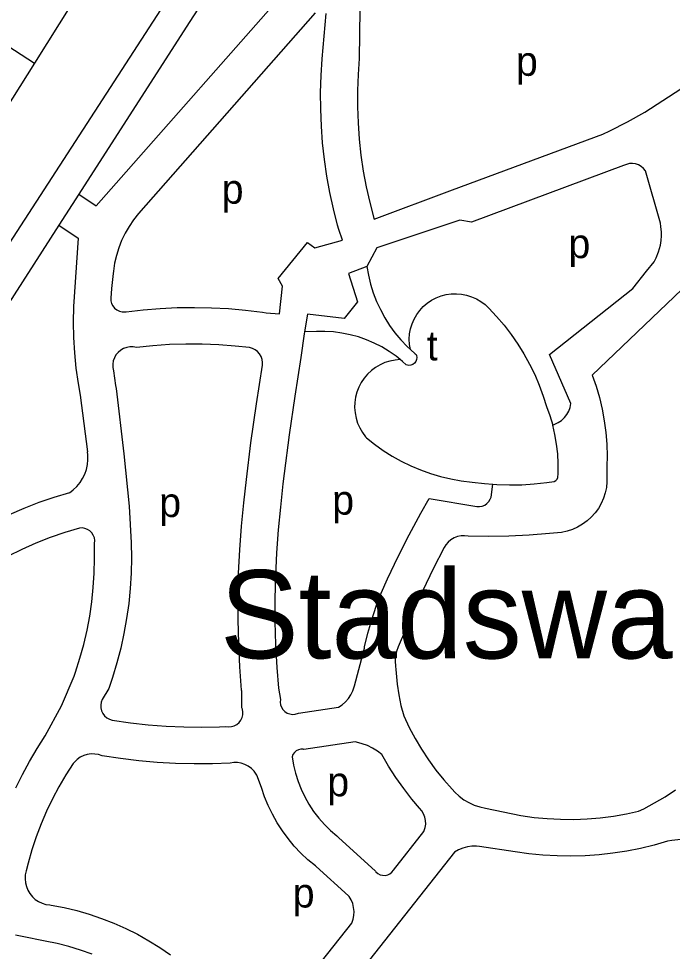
# Model space of a CAD drawing. Extents: x 161141 to 163125, y 381621 to 383200.
# Drawn here: x 161502.1 to 161591, y 381873.7 to 382000.5 of the extents above; entities that cross this region are included whole.
import ezdxf

# ---------------------------------------------------------------- set-up
doc = ezdxf.new("R2010")
doc.units = 0
for name, color, linetype in [('BLT_Basislijn', 7, 'Continuous'), ('BLT_Centroide', 7, 'Continuous'), ('BLT_Sport_parknaam', 7, 'Continuous')]:
    doc.layers.add(name, color=color, linetype=linetype)

msp = doc.modelspace()

# ---------------------------------------------------------------- linework, layer by layer
at = {"layer": 'BLT_Basislijn'}
for p, q in [((161478.82, 381936.02), (161528.43, 382012.47)), ((161509.31, 382002.51), (161504.27, 381994.49)), ((161499.76, 381997.41), (161504.27, 381994.49)), ((161510.29, 381976.65), (161507.59, 381972.44)), ((161507.59, 381972.44), (161460.42, 381899.15)), ((161507.59, 381972.44), (161510.24, 381970.68)), ((161510.24, 381970.68), (161509.59, 381961.37)), ((161510.47, 381949.31), (161511.48, 381941.63))]:
    msp.add_line(p, q, dxfattribs=at)
for points in [[(161510.29, 381976.65), (161512.67, 381975.06), (161540.81, 382007.02), (161543.84, 382010.43), (161567.14, 382036.81), (161578.53, 382051.26), (161578.78, 382051.57), (161578.98, 382051.94), (161579.1, 382052.33), (161579.14, 382052.74), (161579.1, 382053.16), (161578.99, 382053.55), (161578.8, 382053.92), (161578.54, 382054.24), (161578.23, 382054.51), (161577.87, 382054.71), (161567.03, 382064.29)], [(161567.03, 382064.29), (161566.63, 382063.69), (161525.32, 382000), (161510.29, 381976.65)], [(161587.29, 381987.83), (161601.2, 381996.85), (161601.52, 381997.05), (161601.84, 381997.33), (161602.09, 381997.67), (161602.27, 381998.05), (161602.39, 381998.45), (161602.42, 381998.87), (161602.37, 381999.29), (161602.24, 381999.69), (161602.04, 382000.06), (161571.03, 382028.64)], [(161548.56, 382005.09), (161548.43, 381995.12), (161548.27, 381992.93), (161548.19, 381990.74), (161548.19, 381988.54), (161548.27, 381986.35), (161548.43, 381984.16), (161548.67, 381981.98), (161548.99, 381979.81), (161549.39, 381977.65), (161549.86, 381975.51), (161550.42, 381973.38), (161550.46, 381973.24), (161561.11, 381977.23), (161581.58, 381984.83), (161582.51, 381985.28), (161584.92, 381986.52), (161587.29, 381987.83)], [(161542.45, 382001.33), (161518.42, 381974.02), (161517.74, 381973.17), (161517.14, 381972.27), (161516.6, 381971.34), (161516.13, 381970.36), (161515.74, 381969.35), (161515.42, 381968.32), (161515.18, 381967.26), (161515.01, 381966.19), (161514.98, 381965.85), (161514.76, 381963.85), (161514.65, 381962.52), (161514.67, 381962.15), (161514.77, 381961.78), (161514.95, 381961.45), (161515.18, 381961.15), (161515.48, 381960.92), (161515.82, 381960.75), (161516.18, 381960.66), (161516.56, 381960.64), (161516.74, 381960.67), (161519.05, 381960.93), (161521.37, 381961.12), (161523.69, 381961.23), (161526.02, 381961.26), (161528.34, 381961.22), (161530.67, 381961.09), (161532.98, 381960.88), (161535.29, 381960.59), (161535.8, 381960.51), (161537.6, 381960.36), (161538.01, 381964.13), (161537.4, 381965.18), (161541.41, 381970.1), (161542.41, 381969.37), (161546.17, 381970.38), (161545.65, 381971.87)], [(161545.65, 381971.87), (161545.49, 381972.43), (161544.93, 381974.65), (161544.44, 381976.88), (161544.04, 381979.13), (161543.71, 381981.39), (161543.46, 381983.66), (161543.29, 381985.93), (161543.2, 381988.22), (161543.19, 381990.5), (161543.26, 381992.79), (161543.41, 381995.06), (161543.95, 382001.24)], [(161504.27, 381994.49), (161492.03, 381975.07)], [(161574.74, 381945.25), (161575.02, 381945.35), (161575.5, 381945.59), (161575.94, 381945.89), (161576.33, 381946.26), (161576.66, 381946.68), (161576.92, 381947.15), (161577.11, 381947.64), (161577.22, 381948.17), (161574.32, 381954.84), (161585.64, 381963.85), (161587.52, 381966.17), (161588.52, 381967.45), (161588.8, 381967.98), (161589.13, 381968.8), (161589.41, 381969.72), (161589.51, 381970.36), (161589.55, 381970.99), (161589.54, 381971.51), (161589.46, 381972.26), (161589.41, 381972.7), (161587.38, 381979.82), (161587.11, 381980.15), (161586.79, 381980.43), (161586.43, 381980.64), (161586.02, 381980.77), (161585.61, 381980.83), (161585.18, 381980.81), (161584.77, 381980.71), (161584.39, 381980.54), (161563.72, 381972.86), (161562.13, 381973.14), (161550.81, 381969.36), (161549.46, 381966.84)], [(161549.46, 381966.84), (161546.99, 381965.85), (161548.18, 381962.02), (161546.37, 381959.76), (161541.4, 381960.34), (161540.98, 381957.94)], [(161549.46, 381966.84), (161549.68, 381965.62), (161549.98, 381964.41), (161550.35, 381963.23), (161550.8, 381962.07), (161551.32, 381960.95), (161551.91, 381959.86), (161552.57, 381958.81), (161553.3, 381957.81), (161554.09, 381956.86), (161554.94, 381955.96), (161555.39, 381955.53)], [(161592.31, 381963.67), (161580.13, 381952.04), (161580.65, 381950.52), (161581.1, 381948.98), (161581.46, 381947.41), (161581.75, 381945.83), (161581.96, 381944.24), (161582.09, 381942.63), (161582.14, 381941.02), (161582.12, 381939.65), (161582.12, 381937.54), (161582.04, 381936.77), (161581.88, 381936.02), (161581.64, 381935.29), (161581.33, 381934.59), (161580.95, 381933.92), (161580.5, 381933.3), (161579.98, 381932.73), (161579.42, 381932.21), (161578.8, 381931.76), (161578.13, 381931.37), (161577.43, 381931.05), (161576.7, 381930.81), (161575.95, 381930.65), (161574.31, 381930.49), (161571.55, 381930.28), (161568.79, 381930.15), (161566.03, 381930.11), (161563.26, 381930.14), (161562.77, 381930.2), (161562.28, 381930.17), (161561.8, 381930.07), (161561.34, 381929.89), (161560.91, 381929.64), (161560.53, 381929.32), (161560.21, 381928.95), (161559.99, 381928.61), (161558.5, 381925.7), (161557.07, 381922.75), (161555.72, 381919.77), (161554.44, 381916.75), (161554.02, 381915.71), (161553.74, 381915.1), (161553.52, 381914.47), (161553.39, 381913.81), (161553.34, 381913.14), (161553.36, 381912.47), (161553.43, 381912.02), (161553.46, 381911.48), (161553.6, 381910.01), (161553.81, 381908.55), (161554.11, 381907.1), (161554.49, 381905.68)], [(161555.39, 381955.53), (161555.27, 381956.23), (161555.24, 381956.93), (161555.29, 381957.64), (161555.42, 381958.33), (161555.62, 381959.01), (161555.9, 381959.66), (161556.25, 381960.27), (161556.67, 381960.85), (161557.15, 381961.36), (161557.69, 381961.83), (161558.27, 381962.22), (161558.9, 381962.55), (161559.56, 381962.81), (161560.24, 381962.99), (161560.94, 381963.1), (161561.65, 381963.12), (161562.35, 381963.06), (161563.04, 381962.93), (161563.72, 381962.71), (161564.36, 381962.43), (161564.97, 381962.07), (161565.54, 381961.64), (161566.04, 381961.17), (161567.12, 381960.02), (161568.15, 381958.82), (161569.11, 381957.57), (161570.01, 381956.27), (161570.84, 381954.93), (161571.6, 381953.55), (161572.3, 381952.13), (161572.91, 381950.67), (161573.46, 381949.19), (161573.9, 381947.78), (161574.36, 381946.54), (161574.74, 381945.25)], [(161509.59, 381961.37), (161509.55, 381959.27), (161509.6, 381957.17), (161509.72, 381955.07), (161509.92, 381952.98), (161510.2, 381950.9), (161510.47, 381949.31)], [(161540.98, 381957.94), (161540.93, 381957.64), (161540.5, 381954.43), (161539.66, 381949.18), (161538.9, 381943.92), (161538.22, 381938.65), (161538.05, 381937.27), (161537.73, 381934.09), (161537.42, 381930.98), (161537.18, 381927.87), (161537.03, 381924.75), (161536.96, 381921.63), (161536.97, 381918.5), (161537.06, 381915.38), (161537.23, 381912.26), (161537.44, 381909.48), (161537.71, 381907.94), (161537.68, 381907.57), (161537.74, 381907.2), (161537.87, 381906.86), (161538.07, 381906.54), (161538.33, 381906.28), (161538.65, 381906.08), (161539, 381905.95), (161539.37, 381905.9), (161539.74, 381905.92), (161540.18, 381906.07), (161545.63, 381906.86), (161546.13, 381907.2), (161546.58, 381907.59), (161546.98, 381908.04), (161547.31, 381908.54), (161547.57, 381909.08), (161547.75, 381909.65), (161547.79, 381909.78), (161549.14, 381914.92), (161549.17, 381915.06), (161549.62, 381916.93), (161550.14, 381918.77), (161550.74, 381920.6), (161551.41, 381922.39), (161552.3, 381924.34), (161553.73, 381927.35), (161555.24, 381930.32), (161556.82, 381933.26), (161557.94, 381935.24), (161564.43, 381934.18), (161564.8, 381934.16), (161565.16, 381934.22), (161565.51, 381934.36), (161565.81, 381934.57), (161566.07, 381934.84), (161566.26, 381935.15), (161566.36, 381935.44), (161566.62, 381937.19)], [(161554.01, 381954.15), (161553.45, 381954.61), (161552.5, 381955.28), (161551.51, 381955.87), (161550.48, 381956.4), (161549.42, 381956.86), (161548.32, 381957.24), (161547.21, 381957.54), (161546.07, 381957.77), (161544.92, 381957.92), (161543.77, 381957.99), (161542.61, 381957.98), (161540.98, 381957.94)], [(161532.46, 381909.03), (161532.45, 381909.21), (161532.21, 381912.38), (161532.05, 381915.57), (161531.96, 381918.75), (161531.96, 381921.94), (161532.04, 381925.12), (161532.2, 381928.3), (161532.44, 381931.48), (161532.76, 381934.65), (161533.09, 381937.86), (161533.71, 381942.83), (161534.45, 381948.13), (161535.27, 381953.41), (161535.29, 381953.78), (161535.23, 381954.19), (161535.1, 381954.58), (161534.89, 381954.93), (161534.62, 381955.24), (161534.29, 381955.49), (161533.92, 381955.67), (161533.53, 381955.78), (161531.56, 381955.99), (161529.33, 381956.16), (161527.1, 381956.25), (161524.86, 381956.26), (161522.62, 381956.19), (161520.39, 381956.04), (161518.16, 381955.81), (161517.72, 381955.89), (161517.26, 381955.89), (161516.82, 381955.81), (161516.39, 381955.66), (161516, 381955.43), (161515.65, 381955.14), (161515.36, 381954.79), (161515.14, 381954.4), (161514.99, 381953.97), (161514.91, 381953.53), (161514.92, 381953.08), (161515.01, 381952.62), (161515.31, 381950.65), (161515.39, 381950.22), (161516.42, 381941.34), (161517.14, 381934.23), (161517.43, 381929.23), (161517.46, 381927.17), (161517.42, 381925.1), (161517.29, 381923.04), (161517.09, 381920.99), (161516.8, 381918.94), (161516.44, 381916.91), (161516, 381914.89), (161515.48, 381912.89), (161514.88, 381910.91), (161514.38, 381909.43), (161513.48, 381907.94), (161513.34, 381907.57), (161513.28, 381907.17), (161513.3, 381906.77), (161513.4, 381906.38), (161513.58, 381906.02), (161513.82, 381905.7), (161514.12, 381905.43), (161514.47, 381905.23), (161514.85, 381905.1), (161517.34, 381904.74), (161519.75, 381904.47), (161522.17, 381904.29), (161524.6, 381904.18), (161527.02, 381904.15), (161529.45, 381904.21), (161530.31, 381904.24), (161530.69, 381904.2), (161531.08, 381904.24), (161531.45, 381904.35), (161531.79, 381904.54), (161532.09, 381904.79), (161532.33, 381905.1), (161532.5, 381905.45), (161532.59, 381905.83), (161532.61, 381906.21), (161532.55, 381906.6), (161532.49, 381906.78), (161532.46, 381909.03)], [(161555.39, 381955.53), (161556.04, 381954.95), (161556.17, 381954.83), (161556.21, 381954.73), (161556.26, 381954.45), (161556.23, 381954.16), (161556.12, 381953.9), (161555.95, 381953.67), (161555.72, 381953.49), (161555.45, 381953.39), (161555.17, 381953.37), (161554.83, 381953.44), (161554.34, 381953.88), (161554.01, 381954.15)], [(161554.01, 381954.15), (161553.31, 381954.09), (161552.61, 381953.96), (161551.93, 381953.74), (161551.28, 381953.45), (161550.66, 381953.09), (161550.09, 381952.66), (161549.57, 381952.17), (161549.1, 381951.62), (161548.71, 381951.03), (161548.38, 381950.4), (161548.12, 381949.73), (161547.94, 381949.04), (161547.83, 381948.33), (161547.81, 381947.62), (161547.87, 381946.9), (161548, 381946.2), (161548.21, 381945.52), (161548.5, 381944.87), (161548.86, 381944.25), (161549.29, 381943.67), (161549.41, 381943.53), (161550.53, 381942.63), (161551.7, 381941.79), (161552.91, 381941.02), (161554.16, 381940.32), (161555.45, 381939.69), (161556.77, 381939.14), (161558.13, 381938.65), (161559.5, 381938.25), (161560.9, 381937.92), (161562.31, 381937.67), (161563.81, 381937.49), (161565.49, 381937.28), (161566.62, 381937.19)], [(161566.62, 381937.19), (161567.17, 381937.15), (161568.86, 381937.1), (161570.56, 381937.13), (161572.24, 381937.24), (161573.93, 381937.42), (161574.95, 381937.58), (161575.17, 381937.69), (161575.33, 381937.87), (161575.44, 381938.14), (161575.47, 381938.68), (161575.48, 381940.01), (161575.42, 381941.33), (161575.27, 381942.66), (161575.04, 381943.97), (161574.74, 381945.25)], [(161509.02, 381936.05), (161509.55, 381936.45), (161510.04, 381936.91), (161510.47, 381937.42), (161510.83, 381937.98), (161511.12, 381938.59), (161511.34, 381939.22), (161511.49, 381939.87), (161511.55, 381940.54), (161511.53, 381941.21), (161511.48, 381941.63)], [(161509.02, 381936.05), (161506.93, 381935.41), (161504.87, 381934.7), (161502.84, 381933.91), (161500.83, 381933.05), (161498.86, 381932.11), (161496.93, 381931.11), (161495.03, 381930.03), (161493.72, 381929.23)], [(161501.76, 381895.9), (161502.65, 381897.72), (161503.61, 381899.5), (161504.64, 381901.25), (161505.74, 381902.96), (161507.96, 381907.07), (161509.67, 381911.11), (161509.86, 381911.64), (161510.45, 381913.52), (161510.98, 381915.41), (161511.42, 381917.33), (161511.79, 381919.26), (161512.08, 381921.2), (161512.28, 381923.16), (161512.41, 381925.12), (161512.46, 381927.09), (161512.43, 381929.05), (161512.45, 381929.15), (161512.47, 381929.53), (161512.42, 381929.91), (161512.28, 381930.26), (161512.08, 381930.58), (161511.81, 381930.85), (161511.5, 381931.06), (161511.14, 381931.2), (161510.77, 381931.26), (161510.39, 381931.24), (161508.39, 381930.63), (161506.42, 381929.94), (161504.48, 381929.18), (161502.57, 381928.34), (161500.69, 381927.43)], [(161554.49, 381905.68), (161555.22, 381904.13), (161556.03, 381902.61), (161556.9, 381901.14), (161557.84, 381899.71), (161558.85, 381898.32), (161559.93, 381896.98), (161561.06, 381895.7), (161561.43, 381895.29), (161562.03, 381894.76), (161562.67, 381894.29), (161563.36, 381893.89), (161564.08, 381893.56), (161564.84, 381893.3), (161565.61, 381893.13), (161570.43, 381892.13), (161572.22, 381891.88), (161574.01, 381891.71), (161575.81, 381891.62), (161577.61, 381891.61), (161579.41, 381891.68), (161581.21, 381891.83), (161582.99, 381892.06), (161584.77, 381892.36), (161586.43, 381892.73), (161587.12, 381893.06), (161588.6, 381893.85), (161590.05, 381894.7), (161591.44, 381895.62)], [(161556.63, 381893.14), (161555.59, 381894.38), (161554.48, 381895.82), (161553.42, 381897.32), (161552.43, 381898.86), (161551.52, 381900.43), (161550.9, 381900.91), (161550.25, 381901.31), (161549.56, 381901.65), (161548.83, 381901.91), (161548.08, 381902.1), (161547.87, 381902.14), (161540.9, 381901.12), (161540.8, 381901.14), (161540.48, 381901.15), (161540.16, 381901.07), (161539.87, 381900.93), (161539.62, 381900.71), (161539.43, 381900.44), (161539.32, 381900.14), (161539.51, 381899), (161539.78, 381897.88), (161540.12, 381896.78), (161540.54, 381895.71), (161541.04, 381894.66), (161541.6, 381893.66), (161542.24, 381892.7), (161542.94, 381891.78), (161543.7, 381890.91), (161544.52, 381890.1), (161545.39, 381889.35), (161545.63, 381889.16), (161550.63, 381884.57), (161550.71, 381884.47), (161550.98, 381884.24), (161551.29, 381884.08), (161551.62, 381884), (161551.97, 381883.99), (161552.31, 381884.07), (161552.62, 381884.22), (161552.89, 381884.44), (161553.1, 381884.71), (161557.24, 381889.96), (161557.42, 381890.5), (161557.48, 381890.98), (161557.46, 381891.45), (161557.36, 381891.92), (161557.19, 381892.37), (161556.94, 381892.78), (161556.63, 381893.14)], [(161547.41, 381877.51), (161547.59, 381878.02), (161547.7, 381878.55), (161547.73, 381879.1), (161547.68, 381879.64), (161547.55, 381880.17), (161547.34, 381880.67), (161547.06, 381881.14), (161547, 381881.23), (161542.56, 381885.21), (161542.48, 381885.28), (161541.46, 381886.12), (161540.51, 381887.02), (161539.61, 381887.98), (161538.77, 381888.99), (161537.99, 381890.05), (161537.27, 381891.16), (161536.63, 381892.3), (161536.06, 381893.49), (161535.56, 381894.7), (161535.13, 381895.95), (161534.52, 381897.64), (161534.44, 381897.77), (161534.13, 381898.19), (161533.77, 381898.55), (161533.35, 381898.86), (161532.89, 381899.09), (161532.4, 381899.25), (161531.9, 381899.34), (161531.38, 381899.34), (161530.87, 381899.27), (161528.49, 381899.17), (161525.98, 381899.15), (161523.47, 381899.21), (161520.96, 381899.35), (161518.47, 381899.57), (161515.98, 381899.87), (161513.49, 381900.25), (161513, 381900.42), (161512.49, 381900.5), (161511.98, 381900.51), (161511.46, 381900.44), (161510.97, 381900.29), (161510.5, 381900.06), (161510.08, 381899.77), (161509.7, 381899.41), (161509.56, 381899.23), (161508.54, 381897.66), (161507.59, 381896.05), (161506.71, 381894.4), (161505.9, 381892.72), (161505.17, 381891), (161504.5, 381889.25), (161503.92, 381887.47), (161503.41, 381885.67), (161503.14, 381884.59), (161503.03, 381884.06), (161503, 381883.53), (161503.05, 381882.99), (161503.18, 381882.47), (161503.38, 381881.97), (161503.65, 381881.51), (161503.99, 381881.09), (161504.39, 381880.73), (161504.84, 381880.43), (161505.33, 381880.2), (161505.84, 381880.05), (161506.38, 381879.97), (161506.57, 381879.96), (161508.31, 381879.62), (161510.03, 381879.2), (161511.73, 381878.71), (161513.41, 381878.14), (161515.06, 381877.49), (161516.68, 381876.77), (161518.27, 381875.98), (161519.82, 381875.11), (161521.33, 381874.18), (161522.79, 381873.18)], [(161592.15, 381888.87), (161590.96, 381888.73), (161590.37, 381888.63), (161588.56, 381888.11), (161586.7, 381887.66), (161584.83, 381887.29), (161582.94, 381887), (161581.05, 381886.79), (161579.14, 381886.66), (161577.23, 381886.61), (161575.33, 381886.64), (161573.42, 381886.74), (161571.52, 381886.93), (161569.63, 381887.2), (161564.81, 381887.91), (161564.39, 381887.95), (161563.76, 381887.95), (161563.14, 381887.87), (161562.53, 381887.71), (161561.95, 381887.47), (161561.41, 381887.17), (161539.62, 381859.57)], [(161535.91, 381862.95), (161547.41, 381877.51)], [(161512.1, 381873.29), (161510.54, 381873.84), (161508.96, 381874.32), (161507.35, 381874.71), (161505.72, 381875.03), (161502.62, 381875.7), (161501.7, 381875.87)]]:
    msp.add_lwpolyline(points, dxfattribs=at)

# ---------------------------------------------------------------- texts
at = {"layer": 'BLT_Centroide'}
for s, p in [('p', (161569.74, 381992.76)), ('p', (161529.73, 381975.37)), ('p', (161576.88, 381967.96)), ('t', (161557.63, 381954.05)), ('p', (161521.24, 381932.74)), ('p', (161544.76, 381933.07)), ('p', (161544.09, 381894.75)), ('p', (161539.39, 381879.62))]:
    msp.add_text(s, height=4, dxfattribs=at).set_placement(p)
at = {"layer": 'BLT_Sport_parknaam'}
msp.add_text('Stadswandelpark', height=12, dxfattribs=at).set_placement((161529.5, 381913.51))

doc.saveas('drawing.dxf')
